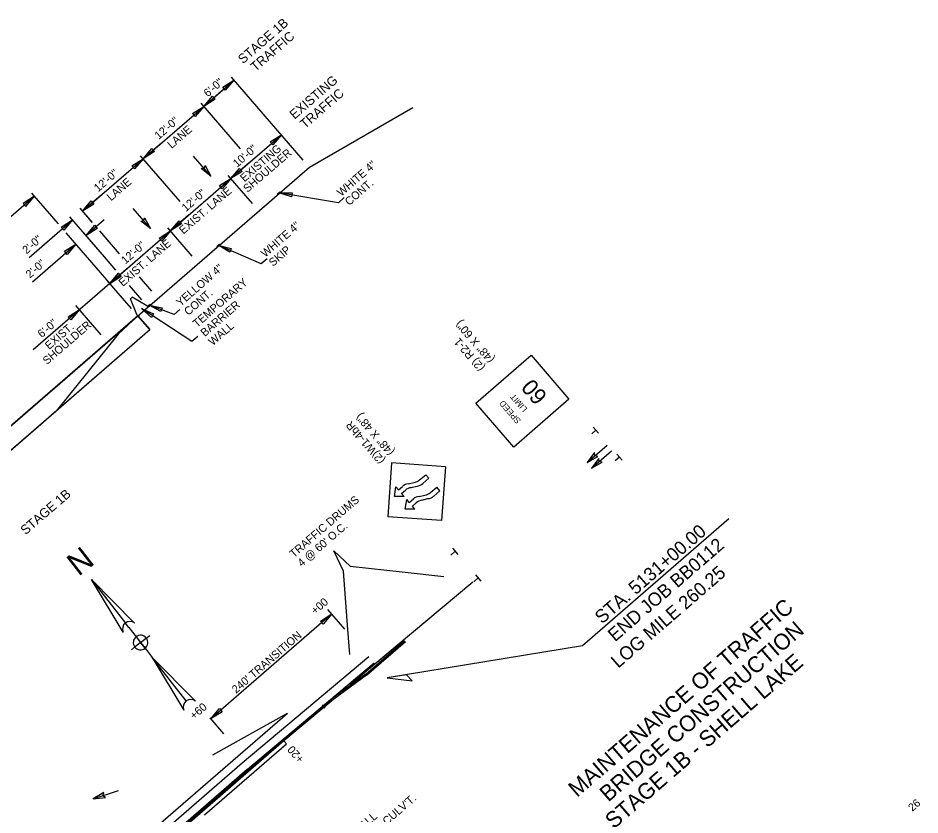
# Model space of a CAD drawing. Extents: x 259983 to 267998, y 211467 to 219827.
# Drawn here: x 262447 to 263799, y 218123 to 219317 of the extents above; entities that cross this region are included whole.
import ezdxf

# ---------------------------------------------------------------- set-up
doc = ezdxf.new("R2010")
doc.units = 0
for name, color, linetype in [('1', 7, 'Continuous'), ('Default', 7, 'Continuous'), ('DRAINAGE', 7, 'Continuous'), ('Level 1', 7, 'Continuous'), ('Level 24', 7, 'Continuous'), ('Level 43', 7, 'Continuous'), ('Level 58', 7, 'Continuous'), ('Level 59', 7, 'Continuous'), ('Level 6', 7, 'Continuous'), ('R_Border Notes', 7, 'Continuous'), ('R_MOT', 7, 'Continuous'), ('R_MOT STAGE 1', 7, 'Continuous'), ('R_MOT STAGE 2', 7, 'Continuous')]:
    doc.layers.add(name, color=color, linetype=linetype)

msp = doc.modelspace()

# ---------------------------------------------------------------- linework, layer by layer
at = {"layer": '1'}
for p, q in [((262725.3, 219184.3), (262770.6, 219223.6)), ((262874.2, 219103.9), (262766.7, 219228.1)), ((262752.5, 219207.9), (262725.3, 219184.3)), ((262634.5, 219105.8), (262725.3, 219184.3)), ((262780.6, 219120.4), (262721.3, 219188.9)), ((262766, 219076.1), (262841.6, 219141.6)), ((262661.8, 219129.3), (262634.5, 219105.8)), ((262543.8, 219027.2), (262634.5, 219105.8)), ((262689.9, 219041.9), (262630.6, 219110.3)), ((262793.2, 219099.7), (262766, 219076.1)), ((262675.3, 218997.6), (262766, 219076.1)), ((262798.6, 219038.5), (262762.1, 219080.7)), ((262471.6, 219049.6), (262018, 218656.9)), ((262507.5, 219008.1), (262467.6, 219054.1)), ((262571, 219050.8), (262543.8, 219027.2)), ((262571, 219050.8), (262543.8, 219027.2)), ((262927.2, 219039.8), (262837.8, 219054.9)), ((262936, 219047.5), (262927.2, 219039.8)), ((262557.2, 219011.8), (262539.9, 219031.8)), ((262558.6, 219010.2), (262539.9, 219031.8)), ((262576.8, 218958.6), (262524.8, 219018.7)), ((262702.5, 219021.2), (262675.3, 218997.6)), ((262463.7, 218957.9), (262528.7, 219014.1)), ((262576.1, 219014.4), (262548.9, 218990.9)), ((262586.4, 218916.9), (262519.2, 218994.6)), ((262566.9, 218970), (262544.9, 218995.4)), ((262599.1, 218963.4), (262569.4, 218997.7)), ((262599.1, 218963.4), (262574.4, 218991.9)), ((262584.6, 218919.1), (262675.3, 218997.6)), ((262707.9, 218959.9), (262671.4, 219002.1)), ((262468.8, 218921.5), (262533.7, 218977.8)), ((262811.6, 218948.3), (262747.1, 218976.4)), ((262593.8, 218939), (262576.8, 218958.6)), ((262820.4, 218956), (262811.6, 218948.3)), ((262611.8, 218942.6), (262584.6, 218919.1)), ((262617.2, 218881.4), (262580.6, 218923.6)), ((262647.4, 218907.6), (262629, 218928.8)), ((262584.6, 218919.1), (262469.5, 218819.4)), ((262632.3, 218894.5), (262613.9, 218915.7)), ((262571.8, 218842.1), (262533.8, 218886)), ((262680.8, 218872.3), (262643.4, 218886.6)), ((262707.7, 218832), (262632, 218881.4)), ((262689.6, 218880), (262680.8, 218872.3)), ((262716.6, 218839.6), (262707.7, 218832))]:
    msp.add_line(p, q, dxfattribs=at)
for points in [[(262753.7, 219212.9), (262770.6, 219223.6), (262757.6, 219208.4)], [(262742.2, 219195), (262725.3, 219184.3), (262738.3, 219199.6)], [(262708.3, 219173.6), (262725.3, 219184.3), (262712.3, 219169.1)], [(262824.7, 219130.9), (262841.6, 219141.6), (262828.6, 219126.4)], [(262651.5, 219116.5), (262634.5, 219105.8), (262647.5, 219121)], [(262617.6, 219095.1), (262634.5, 219105.8), (262621.5, 219090.6)], [(262782.9, 219086.8), (262766, 219076.1), (262779, 219091.4)], [(262749.1, 219065.5), (262766, 219076.1), (262753, 219060.9)], [(262458.6, 219034.3), (262471.6, 219049.6), (262454.6, 219038.9)], [(262856.8, 219048.7), (262837.8, 219054.9), (262857.8, 219054.6)], [(262560.8, 219037.9), (262543.8, 219027.2), (262556.8, 219042.5)], [(262560.8, 219037.9), (262543.8, 219027.2), (262556.8, 219042.5)], [(262511.8, 219003.5), (262528.7, 219014.1), (262515.7, 218998.9)], [(262565.8, 219001.5), (262548.9, 218990.9), (262561.9, 219006.1)], [(262692.2, 219008.3), (262675.3, 218997.6), (262688.3, 219012.8)], [(262658.4, 218986.9), (262675.3, 218997.6), (262662.3, 218982.4)], [(262516.8, 218967.1), (262533.7, 218977.8), (262520.7, 218962.5)], [(262764.2, 218965.9), (262747.1, 218976.4), (262766.5, 218971.5)], [(262601.5, 218929.8), (262584.6, 218919.1), (262597.6, 218934.3)], [(262597.6, 218934.3), (262584.6, 218919.1), (262601.5, 218929.8)], [(262660.9, 218876.9), (262643.4, 218886.6), (262663, 218882.5)], [(262522.3, 218869.1), (262539.2, 218879.8), (262526.2, 218864.6)], [(262646.9, 218868.1), (262632, 218881.4), (262650.2, 218873.2)], [(262900.5, 218413.2), (262917.4, 218423.8), (262904.4, 218408.6)], [(262752.9, 218277.4), (262736, 218266.7), (262749, 218282)]]:
    msp.add_lwpolyline(points, close=True, dxfattribs=at)
for points in [[(262941.4, 218400.5), (262934.7, 218487.9), (262920.4, 218518.3), (262944.5, 218495.6), (263027.1, 218486.5)], [(263027.1, 218486.5), (263085.1, 218480.1)], [(262944.3, 218362.9), (262941.4, 218400.5)]]:
    msp.add_lwpolyline(points, dxfattribs=at)
at = {"layer": 'Default'}
for p, q in [((262883.7, 219093), (263038.6, 219182.7)), ((262173.1, 218477.7), (262883.8, 219093)), ((262615.4, 218895.9), (262618.2, 218898.3)), ((262625, 218872.3), (262615.4, 218895.9)), ((262640.2, 218885.4), (262618.2, 218898.3)), ((262641.8, 218883.5), (262640.2, 218885.4)), ((262626.7, 218870.5), (261916, 218255.2)), ((262626.7, 218870.4), (262597.1, 218843.2)), ((262626.7, 218870.4), (262625, 218872.3)), ((262626.7, 218870.4), (262644.5, 218849.8)), ((262190.9, 218457.1), (262644.6, 218849.9)), ((262597.1, 218843.2), (262506.3, 218730.1))]:
    msp.add_line(p, q, dxfattribs=at)
for points in [[(262835.6, 219053), (262839.4, 219056.3), (262840.3, 219055.4), (262836.4, 219052)], [(262744.9, 218974.5), (262748.7, 218977.8), (262749.6, 218976.8), (262745.7, 218973.5)], [(262641.2, 218884.7), (262645, 218888), (262645.9, 218887), (262642, 218883.7)]]:
    msp.add_lwpolyline(points, close=True, dxfattribs=at)
at = {"layer": 'Level 1'}
for p, q in [((262556.9, 218475.3), (262621.7, 218410)), ((262604.6, 218396.6), (262556.9, 218475.3)), ((262556.9, 218475.3), (262607.8, 218410.1)), ((262613.2, 218403.3), (262607.8, 218410.1)), ((262613.2, 218403.3), (262623.9, 218389.5)), ((262623.9, 218389.5), (262630.6, 218380.9)), ((262630.6, 218380.9), (262639.2, 218387.7)), ((262639.2, 218387.7), (262644.3, 218391.7)), ((262639.2, 218387.7), (262639.2, 218387.7)), ((262621.7, 218374), (262616.9, 218370.2)), ((262630.6, 218380.9), (262622.3, 218374.5)), ((262630.6, 218380.9), (262637.3, 218372.4)), ((262637.3, 218372.4), (262630.6, 218380.9)), ((262637.3, 218372.4), (262648, 218358.7)), ((262648, 218358.7), (262695.7, 218279.9)), ((262698.9, 218293.5), (262648, 218358.7)), ((262648, 218358.7), (262712.9, 218293.3))]:
    msp.add_line(p, q, dxfattribs=at)
for centre, radius, start, end in [((262614.7, 218401.3), 11.2, 128, 205.3196), ((262614.7, 218401.3), 11.2, 50.6804, 128), ((262630.6, 218381), 10.9, 128, 218), ((262630.6, 218381), 10.9, 38, 128), ((262630.6, 218381), 10.9, 308, 38), ((262630.6, 218381), 10.9, 218, 308), ((262705.8, 218284.7), 11.2, 128, 205.3196), ((262705.8, 218284.7), 11.2, 50.6804, 128)]:
    msp.add_arc(centre, radius, start, end, dxfattribs=at)
at = {"layer": 'Level 24'}
for points in [[(263512.4, 218566.4), (263292.8, 218376.2)], [(263292.8, 218376.2), (263000.2, 218327.9)]]:
    msp.add_lwpolyline(points, dxfattribs=at)
at = {"layer": 'Level 43'}
for points in [[(262736.1, 219079.8), (262710.1, 219109.8)], [(262645.4, 219001.2), (262619.4, 219031.3)], [(263299.9, 218650.9), (263329.9, 218676.9)], [(263306.5, 218642.2), (263336.5, 218668.2)], [(262559.8, 218146.8), (262597.5, 218159.5)]]:
    msp.add_lwpolyline(points, dxfattribs=at)
at = {"layer": 'Level 58'}
for points in [[(262727.2, 219095.9), (262736.1, 219079.8), (262721.5, 219091), (262726.3, 219091.2)], [(262636.5, 219017.3), (262645.4, 219001.2), (262630.8, 219012.4), (262635.6, 219012.6)], [(263311.1, 218665.6), (263299.9, 218650.9), (263316, 218659.9), (263311.2, 218660.8)], [(263317.6, 218656.8), (263306.5, 218642.2), (263322.5, 218651.2), (263317.8, 218652.1)], [(262575.7, 218156.1), (262559.8, 218146.8), (262578.1, 218149), (262574.1, 218151.6)]]:
    msp.add_lwpolyline(points, close=True, dxfattribs=at)
at = {"layer": 'Level 59'}
msp.add_lwpolyline([(263029.2, 218332.8), (263000.2, 218327.9), (263037.8, 218323.4)], close=True, dxfattribs=at)
at = {"layer": 'R_MOT'}
for p, q in [((263313.1, 218699.2), (263306.7, 218693.6)), ((263309.1, 218703.8), (263317.1, 218694.6)), ((263348.2, 218658.7), (263341.7, 218653.1)), ((263344.2, 218663.3), (263352.2, 218654.1)), ((263006.8, 218650.2), (263001, 218569.4)), ((263087.6, 218644.4), (263006.8, 218650.2)), ((263087.6, 218644.4), (263081.8, 218563.6)), ((263048.9, 218624.6), (263058.1, 218632.4)), ((263053.6, 218619.2), (263062.7, 218627.1)), ((263062.7, 218627.1), (263058.1, 218632.4)), ((263011, 218599.8), (263013.2, 218614.2)), ((263017.1, 218609.7), (263013.2, 218614.2)), ((263017.1, 218609.7), (263023.2, 218615)), ((263031.8, 218618.8), (263040.3, 218620.9)), ((263035.9, 218613.3), (263045, 218615.5)), ((263065.3, 218605.7), (263074.4, 218613.6)), ((263079, 218608.2), (263074.4, 218613.6)), ((263025.6, 218599.8), (263011, 218599.8)), ((263021.7, 218604.3), (263027.5, 218609.3)), ((263025.6, 218599.8), (263021.7, 218604.3)), ((263048.1, 218599.9), (263056.7, 218602)), ((263069.9, 218600.3), (263079, 218608.2)), ((263027.3, 218580.9), (263029.5, 218595.4)), ((263033.4, 218590.9), (263029.5, 218595.4)), ((263033.4, 218590.9), (263039.5, 218596.2)), ((263038, 218585.5), (263043.8, 218590.4)), ((263041.9, 218581), (263038, 218585.5)), ((263052.3, 218594.4), (263061.3, 218596.6)), ((263041.9, 218581), (263027.3, 218580.9)), ((263081.8, 218563.6), (263001, 218569.4)), ((263102.1, 218517.7), (263095.6, 218512.1)), ((263098.1, 218522.3), (263106.1, 218513.1)), ((263136.7, 218477.7), (263130.2, 218472.1)), ((263132.7, 218482.3), (263140.7, 218473))]:
    msp.add_line(p, q, dxfattribs=at)
msp.add_lwpolyline([(263132.9, 218739.6), (263215.8, 218811.3), (263272.6, 218745.6), (263189.8, 218673.9)], close=True, dxfattribs=at)
for centre, major_axis in [((263035.1, 218601.9), (-11.6, 13.4)), ((263039.4, 218596.1), (-11.6, 13.4)), ((263037, 218637.8), (11.6, -13.4)), ((263041.7, 218632.3), (11.6, -13.4)), ((263051.4, 218583), (-11.6, 13.4)), ((263053.3, 218618.9), (11.6, -13.4)), ((263058, 218613.5), (11.6, -13.4)), ((263055.7, 218577.3), (-11.6, 13.4))]:
    msp.add_ellipse(centre, major_axis=major_axis, ratio=0.9, start_param=5.717125, end_param=6.306311, dxfattribs=at)
at = {"layer": 'R_MOT STAGE 1'}
for p, q in [((263128.6, 218471.3), (262944.5, 218317.4)), ((262968, 218333.8), (263026.2, 218384.2)), ((262969.4, 218332.3), (263027.5, 218382.7)), ((262972.9, 218359.7), (262782.9, 218200.4)), ((262790.7, 218191.4), (262980.7, 218350.5)), ((262968, 218333.8), (262919.1, 218298)), ((262969.2, 218332.2), (262920.3, 218296.4)), ((262919.1, 218298), (262844.1, 218235.1)), ((262920.3, 218296.4), (262845.4, 218233.6)), ((262902.8, 218287.5), (262906.9, 218282.8)), ((262072.1, 217601.2), (262850.7, 218275.2)), ((262738.8, 218213), (262850.7, 218275.2)), ((262844.1, 218235.1), (261603.1, 217160.8)), ((262845.4, 218233.6), (261604.4, 217159.3)), ((262845.4, 218233.6), (262530.8, 217961.2)), ((262849.3, 218229.1), (262845.4, 218233.6)), ((262726.5, 218122.7), (262849.3, 218229.1)), ((262782.9, 218200.4), (261594, 217171.3)), ((261601.8, 217162.3), (262790.6, 218191.5))]:
    msp.add_line(p, q, dxfattribs=at)
at = {"layer": 'R_MOT STAGE 2'}
for p, q in [((262917.4, 218423.8), (262736, 218266.7)), ((262937, 218401.2), (262911.5, 218430.7)), ((262755.6, 218244.1), (262734.7, 218268.2))]:
    msp.add_line(p, q, dxfattribs=at)
msp.add_lwpolyline([(262173.1, 218477.7), (262190.9, 218457.1), (262644.6, 218849.9), (262626.7, 218870.5)], close=True, dxfattribs=at)

# ---------------------------------------------------------------- texts
at = {"layer": '1'}
for s, height, rotation, p in [('STAGE 1B', 14, 40.8933, (262784.1, 219247.2)), ('TRAFFIC', 14, 40.8933, (262802.9, 219235.6)), ('6\'-0"', 12, 40.8833, (262731.5, 219197.6)), ('EXISTING', 14, 40.8933, (262861.4, 219164.2)), ('TRAFFIC', 14, 40.8933, (262877, 219150)), ('12\'-0"', 12, 40.8833, (262657.9, 219133.9)), ('LANE', 12, 40.8833, (262677.1, 219120.3)), ('10\'-0"', 12, 40.8833, (262775.4, 219092.2)), ('EXISTING', 12, 40.8833, (262786.2, 219070.3)), ('SHOULDER', 12, 40.8833, (262790.8, 219054.5)), ('WHITE 4"', 12, 40.8833, (262931.4, 219048.5)), ('12\'-0"', 12, 40.8833, (262567.1, 219055.4)), ('LANE', 12, 40.8833, (262586.3, 219041.8)), ('CONT.', 12, 40.8833, (262943.2, 219034.9)), ('EXIST. LANE', 12, 40.8833, (262694.7, 218992.1)), ('12\'-0"', 12, 40.8833, (262698.6, 219025.7)), ('WHITE 4"', 12, 40.8833, (262817.4, 218957.3)), ('2\'-0"', 12, 40.8833, (262459.8, 218962.4)), ('EXIST. LANE', 12, 40.8833, (262604, 218913.6)), ('12\'-0"', 12, 40.8833, (262607.9, 218947.2)), ('SKIP', 12, 40.8833, (262829.2, 218943.7)), ('2\'-0"', 12, 40.8733, (262464.8, 218926.1)), ('YELLOW 4"', 12, 40.8833, (262690.4, 218883.8)), ('TEMPORARY', 12, 40.8833, (262715.2, 218852.2)), ('CONT.', 12, 40.8833, (262702.2, 218870.2)), ('BARRIER', 12, 40.8833, (262726.9, 218838.6)), ('6\'-0"', 12, 40.8833, (262482.6, 218836.9)), ('SHOULDER', 12, 40.8833, (262490.4, 218796.6)), ('EXIST.', 12, 40.8833, (262493.6, 218819.2)), ('WALL', 12, 40.8833, (262738.7, 218825)), ('STAGE 1B', 14, 40.8733, (262458.2, 218541.6)), ('TRAFFIC DRUMS', 12, 40.8745, (262860.4, 218507.3)), ("4 @ 60' O.C.", 12, 40.8745, (262872.2, 218493.6)), ("240' TRANSITION", 12, 40.8733, (262773.8, 218304.1))]:
    msp.add_text(s, height=height, rotation=rotation, dxfattribs=at).set_placement(p)
at = {"layer": 'DRAINAGE'}
for s, p in [('18" X 10\' TEMPORARY CULV\'T.', (262867.6, 217992.5)), ('STA. 5126+00 INSTALL', (262855.9, 218006.1))]:
    msp.add_text(s, height=12, rotation=40.8833, dxfattribs=at).set_placement(p)
at = {"layer": 'Level 1'}
msp.add_text('N', height=34.2, rotation=38, dxfattribs=at).set_placement((262537.6, 218479.4))
at = {"layer": 'Level 24'}
for s, p in [('STA. 5131+00.00', (263322.1, 218407.9)), ('END JOB BB0112', (263341.7, 218381.2)), ('LOG MILE 260.25', (263346.4, 218341.6))]:
    msp.add_text(s, height=20, rotation=40.8833, dxfattribs=at).set_placement(p)
at = {"layer": 'Level 6'}
for s, p in [('MAINTENANCE OF TRAFFIC', (263284.7, 218148.2)), ('BRIDGE CONSTRUCTION', (263331.6, 218141.2)), ('STAGE 1B - SHELL LAKE', (263339.8, 218100.7))]:
    msp.add_text(s, height=24, rotation=40.8733, dxfattribs=at).set_placement(p)
at = {"layer": 'R_Border Notes'}
msp.add_text('26', height=11.78, rotation=40.8833, dxfattribs=at).set_placement((263787.3, 218127.3))
at = {"layer": 'R_MOT'}
for s, height, rotation, p in [('(48" X 60")', 12.129, 130.8555, (263161.7, 218806.1)), ('(2) R2-1', 12.13, 130.8555, (263147.3, 218793.6)), ('60', 24.26, 130.8555, (263241.5, 218750.7)), ('LIMIT', 9.05, 130.8555, (263210.9, 218731.2)), ('SPEED', 9.05, 130.8555, (263201.3, 218713.7)), ('(48" X 48")', 12, 130.8833, (263011.6, 218667.4)), ('(2)W1-4bR', 12, 130.8833, (262997.6, 218654.6))]:
    msp.add_text(s, height=height, rotation=rotation, dxfattribs=at).set_placement(p)
at = {"layer": 'R_MOT STAGE 2'}
for s, rotation, p in [('+00', 40.8821, (262892.4, 218422.2)), ('+60', 40.8821, (262710.7, 218264.9)), ('+20', 130.8821, (262876.5, 218207.1))]:
    msp.add_text(s, height=12, rotation=rotation, dxfattribs=at).set_placement(p)

doc.saveas('drawing.dxf')
